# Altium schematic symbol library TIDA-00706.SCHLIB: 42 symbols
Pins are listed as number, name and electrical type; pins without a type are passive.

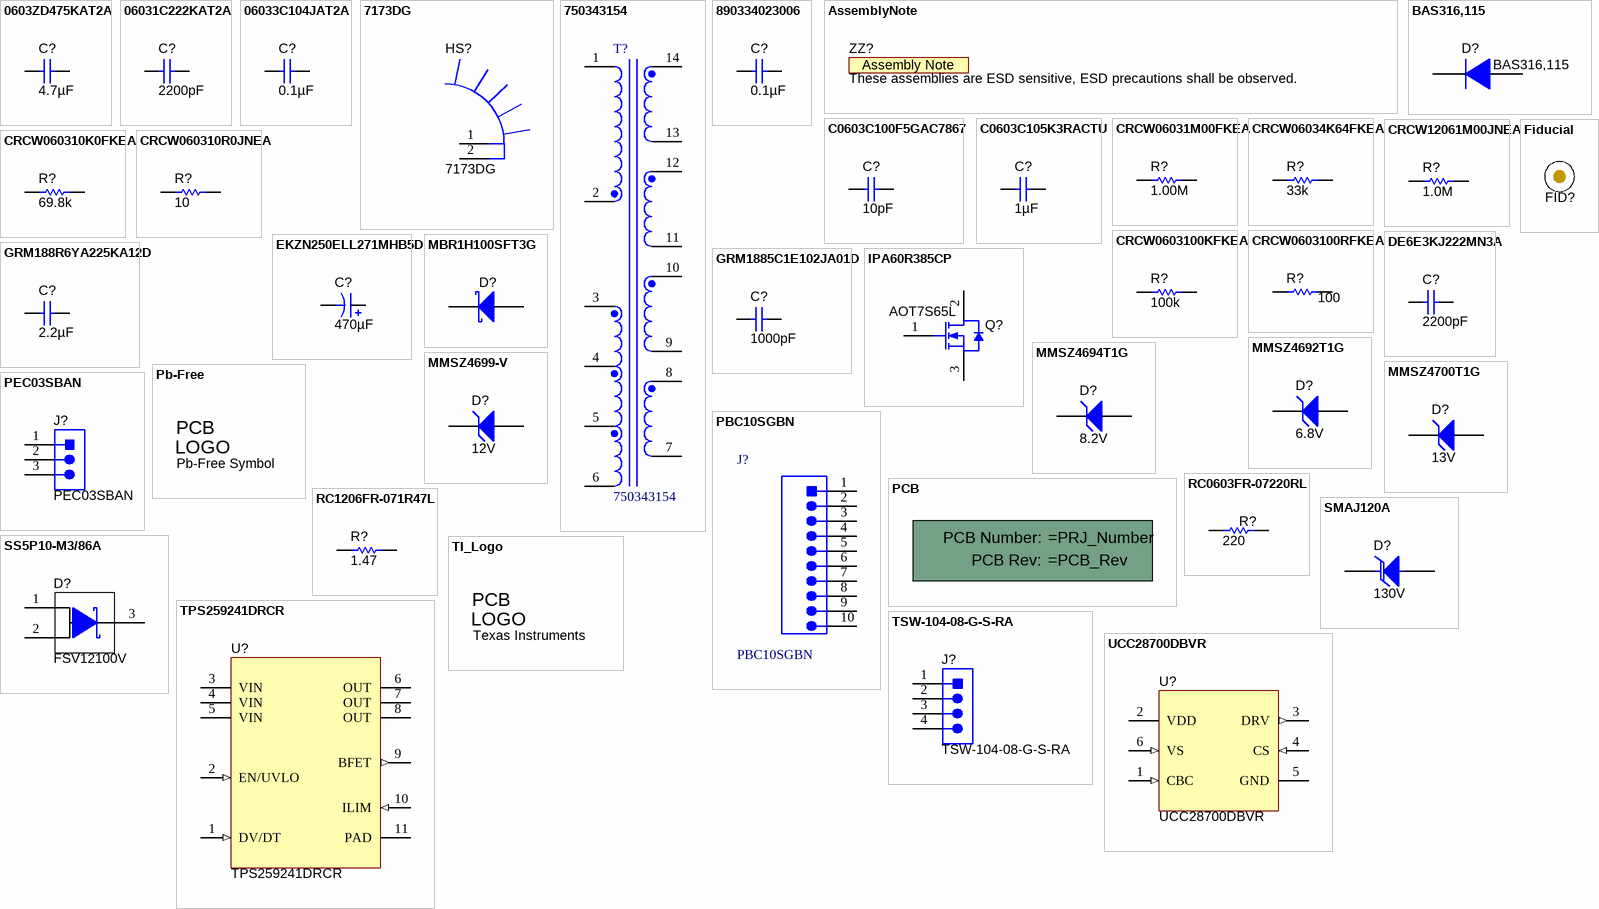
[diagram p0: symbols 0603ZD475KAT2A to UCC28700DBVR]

## 0603ZD475KAT2A
designator C?  ValueDisplayed: 4.7µF  (hidden comment: 0603ZD475KAT2A)
CAP, CERM, 4.7 µF, 10 V, +/- 10%, X5R, 0603; Manufacturer: AVX; Polarized: N; CompType: Capacitor; Value: 4.7uF; U/M: EA; Cap_F: 0.0000047; Tolerance_%: 10; Value1: Unknown; Value2: 10V; TaMin_C: -55; TaMax_C: 85; Cap_Case: 0603; AEC Category: Q200
signal-integrity model Cap
simulation model Cap
footprint 0603
footprint 0603M
footprint 0603L
footprint 0603_HV
footprint 0603S
pins: 1, 2

## 06031C222KAT2A
designator C?  ValueDisplayed: 2200pF  (hidden comment: 06031C222KAT2A)
CAP, CERM, 2200 pF, 100 V, +/- 10%, X7R, 0603; Manufacturer: AVX; Polarized: N; CompType: Capacitor; Value: 2200pF; U/M: EA; Cap_F: 0.0000000022; Tolerance_%: 10; ESR_ohm: 0.192; Value1: 0.192 ohm; VDC_V: 100; Value2: 100V; TaMin_C: -55; TaMax_C: 125; Cap_Case: 0603; AEC Category: Q200
signal-integrity model Cap
simulation model Cap
footprint 0603
footprint 0603M
footprint 0603L
footprint 0603_HV
footprint 0603S
pins: 1, 2

## 06033C104JAT2A
designator C?  ValueDisplayed: 0.1µF  (hidden comment: 06033C104JAT2A)
CAP, CERM, 0.1 µF, 25 V, +/- 5%, X7R, 0603; Manufacturer: AVX; Polarized: N; CompType: Capacitor; Value: 0.1uF; U/M: EA; Cap_F: 0.0000001; Tolerance_%: 5; ESR_ohm: 0.05; Value1: 0.05 ohm; VDC_V: 25; Value2: 25V; TaMin_C: -55; TaMax_C: 125; Cap_Case: 0603; AEC Category: Q200
signal-integrity model Cap
simulation model Cap
footprint 0603
footprint 0603M
footprint 0603L
footprint 0603_HV
footprint 0603S
pins: 1, 2

## 7173DG
designator HS?
Heat Sink, TO-220 Vertical; Manufacturer: Aavid; SymbolCreator: a0799628
footprint HSINK_7173DG
pins: 1, 2

## 750343154
designator T?
footprint XFMR_750343154_CUS (TRANSFORMER, 2.49 MM PITCH, 14-PIN, 16 MM HEIGHT)
pins: 1, 2, 3, 4, 5, 6, 7, 8, 9, 10, 11, 12, 13, 14

## 890334023006
designator C?, comment ValueDisplayed: 0.1µF  (hidden comment: B32671P6104K)
CAP, Film, 0.1 µF, 630 V, +/- 10%, TH; Manufacturer: TDK; Polarized: N; CompType: Capacitor; Value: 0.1uF; U/M: EA; Cap_F: 0.00000001; Tolerance_%: 10; Value1: Unknown; VDC_V: 630; Value2: 630V; TaMin_C: -40; TaMax_C: 105; Cap_Case: 13x5x11mm; AEC Category: Q200
signal-integrity model Cap
simulation model Cap
footprint WCAP-FTXX_P10PL20_13x5x11
pins: 1, 2

## AssemblyNote
designator ZZ?, comment These assemblies are ESD sensitive, ESD precautions shall be observed.  (no BOM)
SymbolCreator: codlsc; CompType: AssemblyNote
footprint AssemblyNote

## BAS316,115
designator D?
Diode, Ultrafast, 100V, 0.25A, SOD-323; Manufacturer: NXP Semiconductor; U/M: EA; Vf_V: 1.4; Value2: 1.4V; Io_A: 0.25; Vr_V: 100; TJmax_C: 150
signal-integrity model Diode
footprint sod-323
pins: 1 K, 2 A

## C0603C100F5GAC7867
designator C?, comment ValueDisplayed: 10pF  (hidden comment: 885012006017)
CAP CER 10PF 16V NP0 0603; Manufacturer: Wurth Electronics Inc; Polarized: N; CompType: Capacitor; U/M: EA; Cap_F: 0.00000000001; Tolerance_%: 1; Value1: Unknown; VDC_V: 10; Value2: 10V; TempCo: C0G/NP0; TaMin_C: -55; TaMax_C: 125; Cap_Case: 0603; AEC Category: Q200
signal-integrity model Cap
simulation model Cap
footprint 0603
footprint 0603M
footprint 0603L
footprint 0603_HV
footprint 0603S
pins: 1, 2

## C0603C105K3RACTU
designator C?  ValueDisplayed: 1µF  (hidden comment: C0603C105K3RACTU)
CAP, CERM, 1 µF, 25 V, +/- 10%, X7R, 0603; Manufacturer: Kemet; Polarized: N; CompType: Capacitor; Value: 1uF; U/M: EA; Cap_F: 0.000001; Tolerance_%: 10; Value1: Unknown; VDC_V: 25; Value2: 25V; TaMin_C: -55; TaMax_C: 125; Cap_Case: 0603; AEC Category: Q200
signal-integrity model Cap
simulation model Cap
footprint 0603
footprint 0603M
footprint 0603L
footprint 0603_HV
footprint 0603S
pins: 1, 2

## CRCW06031M00FKEA
designator R?  ValueDisplayed: 1.00M  (hidden comment: CRCW06031M00FKEA)
RES, 1.00 M, 1%, 0.1 W, 0603; Manufacturer: Vishay-Dale; CompType: Resistor; Value: 1.00Meg; Res_ohm: 1000000; Value_Code: 1M00; Tolerance_%: 1; Power_W: 0.1; Value2: 0.1W; VDC_V: 75; TempCo: 100 ppm/C; EIA_Code: E96; U/M: EA; AEC Category: Q200
signal-integrity model Resistor
simulation model Resistor
footprint 0603
footprint 0603M
footprint 0603L
footprint 0603_HV
footprint 0603S
pins: 1, 2

## CRCW06034K64FKEA
designator R?, comment ValueDisplayed: 33k  (hidden comment: RC0603JR-0733KL)
RES, 33 k, 1%, 0.1 W, 0603; Manufacturer: Yageo; CompType: Resistor; Value: 33k; Res_ohm: 4640; Tolerance_%: 1; Power_W: 0.1; Value2: 0.1W; VDC_V: 75; TempCo: 100 ppm/C; EIA_Code: E96; U/M: EA; AEC Category: Q200
signal-integrity model Resistor
simulation model Resistor
footprint 0603
footprint 0603M
footprint 0603L
footprint 0603_HV
footprint 0603S
pins: 1, 2

## CRCW12061M00JNEA
designator R?  ValueDisplayed: 1.0M  (hidden comment: CRCW12061M00JNEA)
RES, 1.0 M, 5%, 0.25 W, 1206; Manufacturer: Vishay-Dale; CompType: Resistor; Value: 1.0Meg; Res_ohm: 1000000; Value_Code: 1M00; Tolerance_%: 5; Power_W: 0.25; Value2: 0.25W; VDC_V: 200; TempCo: 200 ppm/C; EIA_Code: E24; U/M: EA; AEC Category: Q200
signal-integrity model Resistor
simulation model Resistor
footprint 1206
footprint 1206M
footprint 1206L
pins: 1, 2

## CRCW060310K0FKEA
designator R?, comment ValueDisplayed: 69.8k  (hidden comment: RC0603FR-0769K8L)
RES, 69.8k, 1%, 1/10W, 0603; Manufacturer: Yageo; CompType: Resistor; Res_ohm: 10000; Tolerance_%: 1; Power_W: 0.1; Value2: 0.1W; VDC_V: 75; TempCo: 100 ppm/C; EIA_Code: E96; U/M: EA; AEC Category: Q200
signal-integrity model Resistor
simulation model Resistor
footprint 0603
footprint 0603M
footprint 0603L
footprint 0603_HV
footprint 0603S
pins: 1, 2

## CRCW060310R0JNEA
designator R?  ValueDisplayed: 10  (hidden comment: CRCW060310R0JNEA)
RES, 10, 5%, 0.1 W, 0603; Manufacturer: Vishay-Dale; CompType: Resistor; Value: 10; Value_Code: 10R0; Tolerance_%: 5; Power_W: 0.1; Value2: 0.1W; VDC_V: 75; TempCo: 200 ppm/C; EIA_Code: E24; U/M: EA; AEC Category: Q200
signal-integrity model Resistor
simulation model Resistor
footprint 0603
footprint 0603M
footprint 0603L
footprint 0603_HV
footprint 0603S
pins: 1, 2

## CRCW0603100KFKEA
designator R?  ValueDisplayed: 100k  (hidden comment: CRCW0603100KFKEA)
RES, 100 k, 1%, 0.1 W, 0603; Manufacturer: Vishay-Dale; CompType: Resistor; Value: 100k; Res_ohm: 100000; Tolerance_%: 1; Power_W: 0.1; Value2: 0.1W; VDC_V: 75; TempCo: 100 ppm/C; EIA_Code: E96; U/M: EA; AEC Category: Q200
signal-integrity model Resistor
simulation model Resistor
footprint 0603
footprint 0603M
footprint 0603L
footprint 0603_HV
footprint 0603S
pins: 1, 2

## CRCW0603100RFKEA
designator R?  ValueDisplayed: 100  (hidden comment: CRCW0603100RFKEA)
RES, 100, 1%, 0.1 W, 0603; Manufacturer: Vishay-Dale; CompType: Resistor; Value: 100; Value_Code: 100R; Tolerance_%: 1; Power_W: 0.1; Value2: 0.1W; VDC_V: 75; TempCo: 100 ppm/C; EIA_Code: E96; U/M: EA; AEC Category: Q200
signal-integrity model Resistor
simulation model Resistor
footprint 0603
footprint 0603M
footprint 0603L
footprint 0603_HV
footprint 0603S
pins: 1, 2

## DE6E3KJ222MN3A
designator C?, comment ValueDisplayed: 2200pF  (hidden comment: CS80ZU2GA222MYNKA)
CAP CER 2200PF 300VAC 20% RADIAL; Manufacturer: TDK Corporation; Polarized: N; CompType: Capacitor; Value: 2.2nF; U/M: EA; Cap_F: 0.0000000022; Tolerance_%: 20; Value1: Unknown; VDC_V: 300; Value2: 300V; TempCo: E; TaMin_C: -40; TaMax_C: 125
signal-integrity model Cap
simulation model Cap
footprint E_900x700x900
pins: 1, 2

## EKZN250ELL271MHB5D
designator C?, comment ValueDisplayed: 470µF  (hidden comment: EKZN250ELL471MH15D)
CAP, AL, 470 µF, 25 V, +/- 20%, 0.075 ohm, TH; Manufacturer: United Chemi-Con; Polarized: Y; CompType: Capacitor; Value: 470uF; U/M: EA; Cap_F: 0.00047; Tolerance_%: 20; VDC_V: 25; Value2: 25V; ESR_ohm: 0.075; IRMS_A: 1.6; TaMin_C: -40; TaMax_C: 105; Cap_Case: 8x15mm; AEC Category: Q200
signal-integrity model Cap
simulation model Cap
footprint KZN_800x1150
pins: 1 +, 2 -

## Fiducial
designator FID?  (value not drawn)
Fiducial mark.  There is nothing to buy or mount.; SymbolCreator: codlsc
footprint Fiducial10-30
footprint Fiducial10-20
footprint Fiducial15-30
footprint Fiducial20-40
footprint Fiducial6.4-20

## GRM188R6YA225KA12D
designator C?  ValueDisplayed: 2.2µF  (hidden comment: GRM188R6YA225KA12D)
CAP, CERM, 2.2 µF, 35 V, +/- 10%, X5R, 0603; Manufacturer: MuRata; Polarized: N; CompType: Capacitor; Value: 2.2uF; U/M: EA; Cap_F: 0.0000022; Tolerance_%: 10; Value1: Unknown; VDC_V: 35; Value2: 35V; TaMin_C: -55; TaMax_C: 85; Cap_Case: 0603; AEC Category: Q200
signal-integrity model Cap
simulation model Cap
footprint 0603
footprint 0603M
footprint 0603L
footprint 0603_HV
footprint 0603S
pins: 1, 2

## GRM1885C1E102JA01D
designator C?  ValueDisplayed: 1000pF  (hidden comment: GRM1885C1E102JA01D)
CAP, CERM, 1000 pF, 25 V, +/- 5%, C0G/NP0, 0603; Manufacturer: MuRata; Polarized: N; CompType: Capacitor; Value: 1000pF; U/M: EA; Cap_F: 0.000000001; Tolerance_%: 5; Value1: Unknown; VDC_V: 25; Value2: 25V; TaMin_C: -55; TaMax_C: 125; Cap_Case: 0603; AEC Category: Q200
signal-integrity model Cap
simulation model Cap
footprint 0603
footprint 0603M
footprint 0603L
footprint 0603_HV
footprint 0603S
pins: 1, 2

## IPA60R385CP
designator Q?, comment AOT7S65L
MOSFET, N-CH, 650 V, 7 A, TO-220; Manufacturer: Alpha & Omega Semiconductor Inc.; Alternate Manufacturer: None; U/M: EA; ChType: N; Value: 650V; VdsMax_V: 650; Value1: ? ohm; Value2: 9.2 nC; QgTyp_nC: 9.2; Vgs_V: 4; IdsMax_A: 7; AEC Category: Q101
footprint TO-220_FullPAK_Offset (Infineon  PG-TO220-3-31)
pins: 1 G, 2 D, 3 S
1 alternate drawing of the same symbol

## MBR1H100SFT3G
designator D?, comment MBR2H200SFT1G  (value not drawn)
Diode, Schottky, 200 V, 2 A, SOD-123FL; Manufacturer: ON Semiconductor; U/M: EA; Vf_V: 0.94; Value: 200V; Value1: 2A; Value2: 0.94V; Io_A: 1; Vr_V: 200; TJmax_C: 175; RJC_CperW: 85; AEC Category: Q101
signal-integrity model Diode
footprint SOD-123FL
pins: 1 K, 2 A

## MMSZ4692T1G
designator D?  value 6.8V  (hidden comment: MMSZ4692T1G)
Diode, Zener, 6.8 V, 500 mW, SOD-123; Manufacturer: ON Semiconductor; SymbolCreator: a0412235; U/M: EA; Power_W: 0.5; Vz_V: 6.8; Value1: 0.5W; RJA_CperW: 340; AEC Category: Q101
signal-integrity model Diode
footprint SOD-123
pins: 1 K, 2 A

## MMSZ4694T1G
designator D?  value 8.2V  (hidden comment: MMSZ4694T1G)
Diode, Zener, 8.2 V, 500 mW, SOD-123; Manufacturer: ON Semiconductor; SymbolCreator: a0412235; U/M: EA; Power_W: 0.5; Vz_V: 8.2; Value1: 0.5W; RJA_CperW: 340; AEC Category: Q101
signal-integrity model Diode
footprint SOD-123
pins: 1 K, 2 A

## MMSZ4699-V
designator D?  value 12V  (hidden comment: MMSZ4699-V)
Diode, Zener, 12 V, 500 mW, SOD-123; Manufacturer: Vishay-Semiconductor; SymbolCreator: a0412235; U/M: EA; Power_W: 0.5; Vz_V: 12; Value1: 0.5W; RJA_CperW: 67; AEC Category: Q101
signal-integrity model Diode
footprint SOD-123
pins: 1 K, 2 A

## MMSZ4700T1G
designator D?  value 13V  (hidden comment: MMSZ4700T1G)
Diode, Zener, 13 V, 500 mW, SOD-123; Manufacturer: ON Semiconductor; SymbolCreator: a0412235; U/M: EA; Power_W: 0.5; Vz_V: 13; Value1: 0.5W; RJA_CperW: 340; AEC Category: Q101
signal-integrity model Diode
footprint SOD-123
pins: 1 K, 2 A

## Pb-Free
designator Logo?, comment Pb-Free Symbol  (no BOM)
SymbolCreator: a0412235
footprint Pb-Free_Overlay_Medium
footprint Pb-Free_Overlay_Small

## PBC10SGBN
designator J?
CONNECTOR, HEADER, 2.54MM PITCH, 10 POS, RIGHT ANGLE, TH, ROHS; Manufacturer: SULLINS; SymbolCreator: x0199378
footprint SULLINS_PBC10SGBN (CONN,MALE-10PIN 2.54MM PITCH,SINGLEROW,SULLINS)
pins: 1, 2, 3, 4, 5, 6, 7, 8, 9, 10

## PCB
designator !PCB?, comment Printed Circuit Board  (value not drawn)  (mechanical)
Manufacturer: Any; SymbolCreator: a0412235; CompType: PCB
1 alternate drawing of the same symbol

## PEC03SBAN
designator J?
Header, 100mil, 3x1, Tin, R/A, TH; Manufacturer: Sullins Connector Solutions; SymbolCreator: a0799628; U/M: EA
footprint Sullins_PEC03SBAN
footprint Sullins_PEC03SBAN_REVERSED
pins: 1, 2, 3
2 alternate drawings of the same symbol

## RC0603FR-07220RL
designator R?  ValueDisplayed: 220  (hidden comment: RC0603FR-07220RL)
RES, 220, 1%, 0.1 W, 0603; Manufacturer: Yageo America; CompType: Resistor; Value: 220; Value_Code: 220R; Tolerance_%: 1; Power_W: 0.1; Value2: 0.1W; VDC_V: 150; TempCo: 200 ppm/C; U/M: EA; AEC Category: Q200
signal-integrity model Resistor
simulation model Resistor
footprint 0603
footprint 0603M
footprint 0603L
footprint 0603_HV
footprint 0603S
pins: 1, 2

## RC1206FR-071R47L
designator R?  ValueDisplayed: 1.47  (hidden comment: RC1206FR-071R47L)
RES, 1.47, 1%, 0.25 W, 1206; Manufacturer: Yageo America; CompType: Resistor; Value: 1.47; Value_Code: 1R47; Tolerance_%: 1; Power_W: 0.25; Value2: 0.25W; VDC_V: 200; TempCo: 200 ppm/C; EIA_Code: E96; U/M: EA; AEC Category: Q200
signal-integrity model Resistor
simulation model Resistor
footprint 1206
footprint 1206M
footprint 1206L
pins: 1, 2

## SMAJ120A
designator D?, comment value 130V  (hidden comment: SMAJ130A-13-F)
Diode, TVS, Uni, 130 V, 400 W, SMA; Manufacturer: Diodes Incorporated; U/M: EA; Power_W: 400; Vr_V: 130; Value1: 400W; AEC Category: Q101
footprint SMA
pins: 1 K, 2 A

## SS5P10-M3/86A
designator D?, comment FSV12100V
DIODE SCHOTTKY 100V 12A TO277-3; Manufacturer: Fairchild Semiconductor; U/M: EA; Vf_V: 0.88; Value2: 0.88V; Io_A: 12; Vr_V: 100
signal-integrity model Diode
footprint TO-277A
pins: 1 A, 2 A, 3 K

## TI_Logo
designator Logo?, comment Texas Instruments  (no BOM)
Texas Instrument Corporate Signature; SymbolCreator: codlsc
footprint TI_Stacked_SolderMask_Medium
footprint TI_Stacked_SolderMask_Small
footprint TI_Stacked_Overlay_Medium
footprint TI_Stacked_Overlay_Small
footprint TI_Horizontal_SolderMask_Medium
footprint TI_Horizontal_SolderMask_Small
footprint TI_Horizontal_Overlay_Medium
footprint TI_Horizontal_Overlay_Small
footprint TI_Symbol_SolderMask_Small
footprint TI_Symbol_Overlay_Medium
footprint TI_Symbol_Overlay_Small
footprint TI_Symbol_SolderMask_Medium

## TPS259241DRCR
designator U?
12-V eFuse with Over Voltage Protection and Blocking FET Control, DRC0010J; Alternate PartNumber: TPS259241DRCT; Manufacturer: Texas Instruments; SymbolCreator: a0799628; CompType: IC; U/M: EA
footprint DRC0010J
pins: 1 DV/DT (in) "dV/dT", 2 EN/UVLO (in), 3 VIN (power), 4 VIN (power), 5 VIN (power), 6 OUT (power), 7 OUT (power), 8 OUT (power), 9 BFET (out), 10 ILIM (in), 11 PAD (power)
1 alternate drawing of the same symbol

## TSW-104-08-G-S-RA
designator J?
Header, 100mil, 4x1, Gold, R/A, TH; Manufacturer: Samtec; SymbolCreator: a0412235; U/M: EA
footprint TSW-104-08-G-S-RA
pins: 1, 2, 3, 4

## UCC28700DBVR
designator U?
Constant-Voltage, Constant-Current Controller With Primary-Side Regulation, DBV0006A; Alternate PartNumber: UCC28700DBVT; Manufacturer: Texas Instruments; SymbolCreator: a0799628; CompType: IC; U/M: EA
footprint DBV0006A_N
footprint DBV0006A_M
footprint DBV0006A_L
pins: 1 CBC (in), 2 VDD (power), 3 DRV (out), 4 CS (in), 5 GND (power), 6 VS (in)

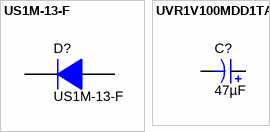
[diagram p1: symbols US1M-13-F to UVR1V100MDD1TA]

## US1M-13-F
designator D?
Diode, Ultrafast, 1000 V, 1 A, SMA; Manufacturer: Diodes Inc.; U/M: EA; Vf_V: 1.7; Value: 1000V; Value1: 1A; Value2: 1.7V; Io_A: 1; Vr_V: 1000; TJmax_C: 150; RJC_CperW: 30; AEC Category: Q101
signal-integrity model Diode
footprint SMA
pins: 1 K, 2 A

## UVR1V100MDD1TA
designator C?, comment ValueDisplayed: 47µF  (hidden comment: UPW1E470MDD)
CAP, AL, 47 µF, 25 V, +/- 20%, TH; Manufacturer: Nichicon; Polarized: Y; CompType: Capacitor; Value: 47uF; U/M: EA; Cap_F: 0.000047; Tolerance_%: 20; Value1: Unknown; VDC_V: 25; Value2: 25V; TaMin_C: -40; TaMax_C: 85; Cap_Case: 5x11; AEC Category: Q200; AEC Qualified: N
signal-integrity model Cap
simulation model Cap
footprint CAPPR2-5x11
pins: 1 +, 2 -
